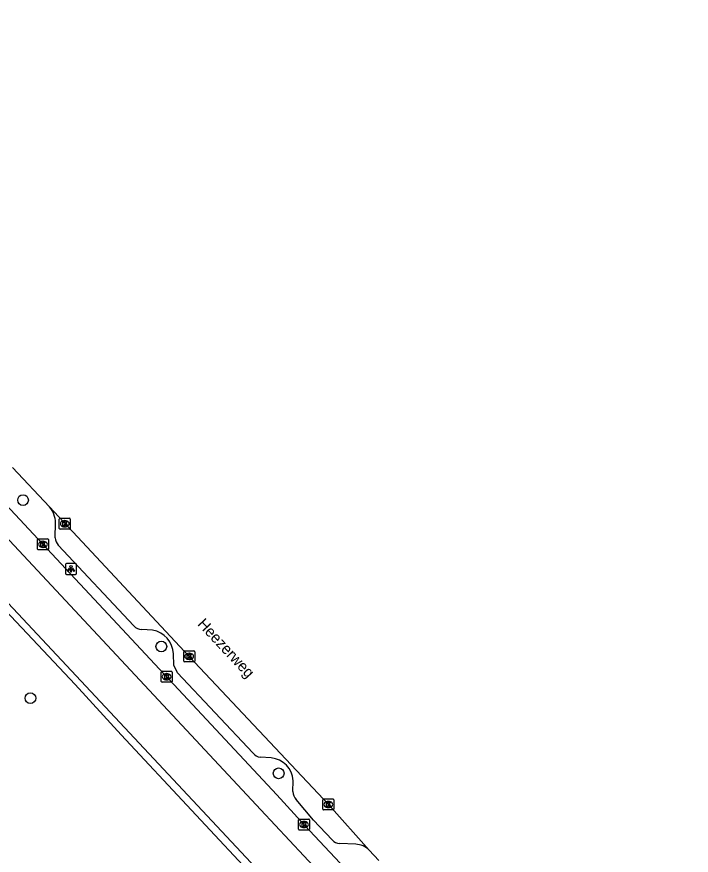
# Model space of a CAD drawing. Extents: x 162675 to 163482, y 379761 to 381227.
# Drawn here: x 163381.1 to 163442.5, y 380937.9 to 381014.2 of the extents above; entities that cross this region are included whole.
import ezdxf

# ---------------------------------------------------------------- set-up
doc = ezdxf.new("R2010")
doc.units = 0
for name, color, linetype in [('IMGEO_Boom', 7, 'Continuous'), ('IMGEO_Fietspad_gesloten', 7, 'Continuous'), ('IMGEO_Groenvoorziening', 7, 'Continuous'), ('IMGEO_Hek', 7, 'Continuous'), ('IMGEO_Kolk', 7, 'Continuous'), ('IMGEO_Lichtpunt', 7, 'Continuous'), ('IMGEO_Openbare_ruimte_label', 7, 'Continuous'), ('IMGEO_Parkeervlak_open', 7, 'Continuous'), ('IMGEO_Rijbaan_lokaal_gesloten', 7, 'Continuous'), ('IMGEO_Voetpad_open', 7, 'Continuous')]:
    doc.layers.add(name, color=color, linetype=linetype)

msp = doc.modelspace()

# ---------------------------------------------------------------- linework, layer by layer
at = {"layer": 'IMGEO_Boom'}
for centre in [(163381.722, 380970.207), (163394.309, 380956.899), (163382.391, 380952.201), (163404.983, 380945.367)]:
    msp.add_circle(centre, 0.489, dxfattribs=at)
at = {"layer": 'IMGEO_Fietspad_gesloten'}
for points in [[(163442.528, 380900.205), (163438.582, 380904.399), (163403.356, 380942.043), (163381.324, 380965.637), (163349.187, 381000), (163303.348, 381049.029), (163302.54, 381049.896), (163269.7, 381085.146), (163222.96, 381135.118), (163217.057, 381141.357)], [(163297.629, 381058.041), (163301.939, 381053.48), (163304.039, 381051.234), (163315.711, 381038.75), (163343.734, 381008.697), (163351.893, 381000), (163369.825, 380980.883), (163383.497, 380966.224), (163404.827, 380943.419), (163407.337, 380940.661), (163420.715, 380926.423), (163421.985, 380925.068)]]:
    msp.add_lwpolyline(points, dxfattribs=at)
at = {"layer": 'IMGEO_Groenvoorziening'}
msp.add_lwpolyline([(163404.993, 380933.536), (163403.462, 380935.161), (163390.657, 380948.856), (163386.451, 380953.455), (163376.71, 380963.784), (163373.198, 380964.214), (163372.923, 380964.017), (163339.792, 380933.51), (163323.416, 380918.477)], dxfattribs=at)
at = {"layer": 'IMGEO_Hek'}
msp.add_lwpolyline([(163390.657, 380948.856), (163403.462, 380935.161)], dxfattribs=at)
at = {"layer": 'IMGEO_Kolk'}
for p, q in [((163385.021, 380967.636), (163385.021, 380968.488)), ((163385.096, 380968.562), (163385.948, 380968.562)), ((163385.509, 380968.342), (163385.534, 380968.342)), ((163386.022, 380968.488), (163386.022, 380967.636)), ((163385.948, 380967.562), (163385.096, 380967.562)), ((163385.532, 380967.782), (163385.507, 380967.782)), ((163383.032, 380965.762), (163383.032, 380966.614)), ((163383.107, 380966.688), (163383.959, 380966.688)), ((163383.52, 380966.468), (163383.545, 380966.468)), ((163384.033, 380966.614), (163384.033, 380965.762)), ((163383.959, 380965.688), (163383.107, 380965.688)), ((163383.543, 380965.908), (163383.518, 380965.908)), ((163396.344, 380955.576), (163396.344, 380956.428)), ((163396.419, 380956.502), (163397.271, 380956.502)), ((163397.345, 380956.428), (163397.345, 380955.576)), ((163396.855, 380955.722), (163396.83, 380955.722)), ((163396.832, 380956.282), (163396.857, 380956.282)), ((163397.271, 380955.502), (163396.419, 380955.502)), ((163394.294, 380953.726), (163394.294, 380954.578)), ((163394.369, 380954.652), (163395.221, 380954.652)), ((163394.782, 380954.432), (163394.807, 380954.432)), ((163395.295, 380954.578), (163395.295, 380953.726)), ((163395.221, 380953.652), (163394.369, 380953.652)), ((163394.805, 380953.872), (163394.78, 380953.872)), ((163409.001, 380942.108), (163409.001, 380942.96)), ((163409.076, 380943.034), (163409.928, 380943.034)), ((163409.489, 380942.814), (163409.514, 380942.814)), ((163410.002, 380942.96), (163410.002, 380942.108)), ((163409.928, 380942.034), (163409.076, 380942.034)), ((163409.512, 380942.254), (163409.487, 380942.254)), ((163406.864, 380941.212), (163407.716, 380941.212)), ((163406.789, 380940.286), (163406.789, 380941.138)), ((163407.3, 380940.432), (163407.275, 380940.432)), ((163407.277, 380940.992), (163407.302, 380940.992)), ((163407.79, 380941.138), (163407.79, 380940.286)), ((163407.716, 380940.212), (163406.864, 380940.212))]:
    msp.add_line(p, q, dxfattribs=at)
for points in [[(163385.021, 380967.636), (163385.021, 380968.488)], [(163385.096, 380968.562), (163385.948, 380968.562)], [(163385.342, 380968.262), (163385.465, 380968.262), (163385.465, 380968.111), (163385.595, 380968.262), (163385.759, 380968.262), (163385.613, 380968.111), (163385.766, 380967.862), (163385.614, 380967.862), (163385.529, 380968.026), (163385.465, 380967.959), (163385.465, 380967.862), (163385.342, 380967.862), (163385.342, 380968.262)], [(163386.022, 380968.488), (163386.022, 380967.636)], [(163385.948, 380967.562), (163385.096, 380967.562)], [(163383.032, 380965.762), (163383.032, 380966.614)], [(163383.107, 380966.688), (163383.959, 380966.688)], [(163383.353, 380966.388), (163383.476, 380966.388), (163383.476, 380966.237), (163383.606, 380966.388), (163383.77, 380966.388), (163383.624, 380966.237), (163383.777, 380965.988), (163383.625, 380965.988), (163383.54, 380966.152), (163383.476, 380966.085), (163383.476, 380965.988), (163383.353, 380965.988), (163383.353, 380966.388)], [(163384.033, 380966.614), (163384.033, 380965.762)], [(163383.959, 380965.688), (163383.107, 380965.688)], [(163396.344, 380955.576), (163396.344, 380956.428)], [(163396.419, 380956.502), (163397.271, 380956.502)], [(163397.345, 380956.428), (163397.345, 380955.576)], [(163396.665, 380956.202), (163396.788, 380956.202), (163396.788, 380956.051), (163396.918, 380956.202), (163397.082, 380956.202), (163396.936, 380956.051), (163397.089, 380955.802), (163396.937, 380955.802), (163396.852, 380955.966), (163396.788, 380955.899), (163396.788, 380955.802), (163396.665, 380955.802), (163396.665, 380956.202)], [(163397.271, 380955.502), (163396.419, 380955.502)], [(163394.294, 380953.726), (163394.294, 380954.578)], [(163394.369, 380954.652), (163395.221, 380954.652)], [(163394.615, 380954.352), (163394.738, 380954.352), (163394.738, 380954.201), (163394.868, 380954.352), (163395.032, 380954.352), (163394.886, 380954.201), (163395.039, 380953.952), (163394.887, 380953.952), (163394.802, 380954.116), (163394.738, 380954.049), (163394.738, 380953.952), (163394.615, 380953.952), (163394.615, 380954.352)], [(163395.295, 380954.578), (163395.295, 380953.726)], [(163395.221, 380953.652), (163394.369, 380953.652)], [(163409.001, 380942.108), (163409.001, 380942.96)], [(163409.076, 380943.034), (163409.928, 380943.034)], [(163409.322, 380942.734), (163409.445, 380942.734), (163409.445, 380942.583), (163409.575, 380942.734), (163409.739, 380942.734), (163409.593, 380942.583), (163409.746, 380942.334), (163409.594, 380942.334), (163409.509, 380942.498), (163409.445, 380942.431), (163409.445, 380942.334), (163409.322, 380942.334), (163409.322, 380942.734)], [(163410.002, 380942.96), (163410.002, 380942.108)], [(163409.928, 380942.034), (163409.076, 380942.034)], [(163406.864, 380941.212), (163407.716, 380941.212)], [(163406.789, 380940.286), (163406.789, 380941.138)], [(163407.11, 380940.912), (163407.233, 380940.912), (163407.233, 380940.761), (163407.363, 380940.912), (163407.527, 380940.912), (163407.381, 380940.761), (163407.534, 380940.512), (163407.382, 380940.512), (163407.297, 380940.676), (163407.233, 380940.609), (163407.233, 380940.512), (163407.11, 380940.512), (163407.11, 380940.912)], [(163407.79, 380941.138), (163407.79, 380940.286)], [(163407.716, 380940.212), (163406.864, 380940.212)]]:
    msp.add_lwpolyline(points, dxfattribs=at)
for centre, start, end in [((163385.098, 380968.486), 91.55205, 178.44795), ((163385.098, 380968.486), 91.55205, 178.44795), ((163385.946, 380968.486), 1.55205, 88.44795), ((163385.946, 380968.486), 1.55205, 88.44795), ((163385.098, 380967.638), 181.55205, 268.44795), ((163385.098, 380967.638), 181.55205, 268.44795), ((163385.946, 380967.638), 271.55205, 358.44795), ((163385.946, 380967.638), 271.55205, 358.44795), ((163383.109, 380966.612), 91.55205, 178.44795), ((163383.109, 380966.612), 91.55205, 178.44795), ((163383.957, 380966.612), 1.55205, 88.44795), ((163383.957, 380966.612), 1.55205, 88.44795), ((163383.109, 380965.764), 181.55205, 268.44795), ((163383.109, 380965.764), 181.55205, 268.44795), ((163383.957, 380965.764), 271.55205, 358.44795), ((163383.957, 380965.764), 271.55205, 358.44795), ((163396.421, 380956.426), 91.55205, 178.44795), ((163396.421, 380956.426), 91.55205, 178.44795), ((163397.269, 380956.426), 1.55205, 88.44795), ((163397.269, 380956.426), 1.55205, 88.44795), ((163396.421, 380955.578), 181.55205, 268.44795), ((163396.421, 380955.578), 181.55205, 268.44795), ((163397.269, 380955.578), 271.55205, 358.44795), ((163397.269, 380955.578), 271.55205, 358.44795), ((163394.371, 380954.576), 91.55205, 178.44795), ((163394.371, 380954.576), 91.55205, 178.44795), ((163395.219, 380954.576), 1.55205, 88.44795), ((163395.219, 380954.576), 1.55205, 88.44795), ((163394.371, 380953.728), 181.55205, 268.44795), ((163394.371, 380953.728), 181.55205, 268.44795), ((163395.219, 380953.728), 271.55205, 358.44795), ((163395.219, 380953.728), 271.55205, 358.44795), ((163409.078, 380942.958), 91.55205, 178.44795), ((163409.078, 380942.958), 91.55205, 178.44795), ((163409.926, 380942.958), 1.55205, 88.44795), ((163409.926, 380942.958), 1.55205, 88.44795), ((163409.078, 380942.11), 181.55205, 268.44795), ((163409.078, 380942.11), 181.55205, 268.44795), ((163409.926, 380942.11), 271.55205, 358.44795), ((163409.926, 380942.11), 271.55205, 358.44795), ((163406.866, 380941.136), 91.55205, 178.44795), ((163406.866, 380941.136), 91.55205, 178.44795), ((163407.714, 380941.136), 1.55205, 88.44795), ((163407.714, 380941.136), 1.55205, 88.44795), ((163406.866, 380940.288), 181.55205, 268.44795), ((163406.866, 380940.288), 181.55205, 268.44795), ((163407.714, 380940.288), 271.55205, 358.44795), ((163407.714, 380940.288), 271.55205, 358.44795)]:
    msp.add_arc(centre, 0.0765, start, end, dxfattribs=at)
for centre, major_axis, ratio, start_param, end_param in [((163385.508, 380968.062), (-0.387, 0.002), 0.722429, 4.712389, 7.853982), ((163385.533, 380968.062), (-0.39, 0.002), 0.717154, 1.570796, 4.712389), ((163383.519, 380966.188), (-0.387, 0.002), 0.722429, 4.712389, 7.853982), ((163383.544, 380966.188), (-0.39, 0.002), 0.717154, 1.570796, 4.712389), ((163396.831, 380956.002), (-0.387, 0.002), 0.722429, 4.712389, 7.853982), ((163396.856, 380956.002), (-0.39, 0.002), 0.717154, 1.570796, 4.712389), ((163394.781, 380954.152), (-0.387, 0.002), 0.722429, 4.712389, 7.853982), ((163394.806, 380954.152), (-0.39, 0.002), 0.717154, 1.570796, 4.712389), ((163409.488, 380942.534), (-0.387, 0.002), 0.722429, 4.712389, 7.853982), ((163409.513, 380942.534), (-0.39, 0.002), 0.717154, 1.570796, 4.712389), ((163407.276, 380940.712), (-0.387, 0.002), 0.722429, 4.712389, 7.853982), ((163407.301, 380940.712), (-0.39, 0.002), 0.717154, 1.570796, 4.712389)]:
    msp.add_ellipse(centre, major_axis=major_axis, ratio=ratio, start_param=start_param, end_param=end_param, dxfattribs=at)
at = {"layer": 'IMGEO_Lichtpunt'}
for p, q in [((163385.588, 380964.359), (163385.588, 380963.552)), ((163385.588, 380964.359), (163385.588, 380963.552)), ((163386.49, 380964.454), (163385.682, 380964.454)), ((163386.49, 380964.454), (163385.682, 380964.454)), ((163386.584, 380963.552), (163386.584, 380964.359)), ((163386.584, 380963.552), (163386.584, 380964.359)), ((163385.682, 380963.458), (163386.49, 380963.458)), ((163385.682, 380963.458), (163386.49, 380963.458))]:
    msp.add_line(p, q, dxfattribs=at)
for points in [[(163385.962, 380964.023), (163386.001, 380963.995), (163385.813, 380963.733), (163385.775, 380963.76), (163385.962, 380964.023)], [(163386.064, 380963.975), (163386.111, 380963.975), (163386.111, 380963.653), (163386.064, 380963.653), (163386.064, 380963.975)], [(163386.174, 380963.995), (163386.212, 380964.022), (163386.399, 380963.76), (163386.36, 380963.732), (163386.174, 380963.995)]]:
    msp.add_lwpolyline(points, dxfattribs=at)
msp.add_circle((163386.087, 380964.157), 0.0994, dxfattribs=at)
for centre, start, end in [((163385.682, 380964.359), 90, 180), ((163385.682, 380964.359), 90, 180), ((163386.49, 380964.359), 0, 90), ((163386.49, 380964.359), 0, 90), ((163385.682, 380963.552), 180, 270), ((163385.682, 380963.552), 180, 270), ((163386.49, 380963.552), 270, 0), ((163386.49, 380963.552), 270, 360)]:
    msp.add_arc(centre, 0.0946, start, end, dxfattribs=at)
at = {"layer": 'IMGEO_Parkeervlak_open'}
for points in [[(163384.645, 380966.79), (163384.682, 380968.144)], [(163391.803, 380958.771), (163384.931, 380966.115)], [(163393.505, 380958.378), (163392.525, 380958.453)], [(163402.639, 380947.217), (163395.77, 380954.508), (163395.445, 380955.211), (163395.4, 380956.222)], [(163404.304, 380946.77), (163403.309, 380946.846)], [(163406.286, 380943.711), (163406.302, 380944.695)], [(163409.857, 380939.318), (163408.168, 380941.12), (163406.584, 380942.988)], [(163412.001, 380938.923), (163410.527, 380938.998)]]:
    msp.add_lwpolyline(points, dxfattribs=at)
for centre, radius, start, end in [((163382.381, 380968.103), 2.301, 1.00969, 40.49918), ((163385.707, 380966.842), 1.063, 182.79216, 223.13295), ((163392.5, 380959.375), 0.922, 220.90031, 271.55815), ((163393.173, 380956.175), 2.228, 1.2003, 81.42692), ((163403.347, 380947.705), 0.86, 214.57603, 267.47462), ((163404.122, 380944.595), 2.182, 2.61691, 85.217), ((163407.423, 380943.757), 1.138, 182.30771, 222.49241), ((163410.531, 380939.868), 0.87, 219.20897, 269.73164), ((163411.931, 380937.103), 1.821, 44.69603, 87.80499)]:
    msp.add_arc(centre, radius, start, end, dxfattribs=at)
at = {"layer": 'IMGEO_Rijbaan_lokaal_gesloten'}
for points in [[(163380.757, 380973.17), (163384.131, 380969.598)], [(163384.131, 380969.598), (163396.853, 380955.996), (163409.545, 380942.489), (163413.226, 380938.384)], [(163413.226, 380938.384), (163414.099, 380937.456)]]:
    msp.add_lwpolyline(points, dxfattribs=at)
at = {"layer": 'IMGEO_Voetpad_open'}
msp.add_lwpolyline([(163374.975, 380967.47), (163378.763, 380963.459), (163378.306, 380963.06), (163378.593, 380962.733), (163407.315, 380932.067), (163408.65, 380930.642)], dxfattribs=at)

# ---------------------------------------------------------------- texts
at = {"layer": 'IMGEO_Openbare_ruimte_label'}
msp.add_text('Heezerweg', height=1, rotation=313.13672, dxfattribs=at).set_placement((163397.535, 380958.887))

doc.saveas('drawing.dxf')
